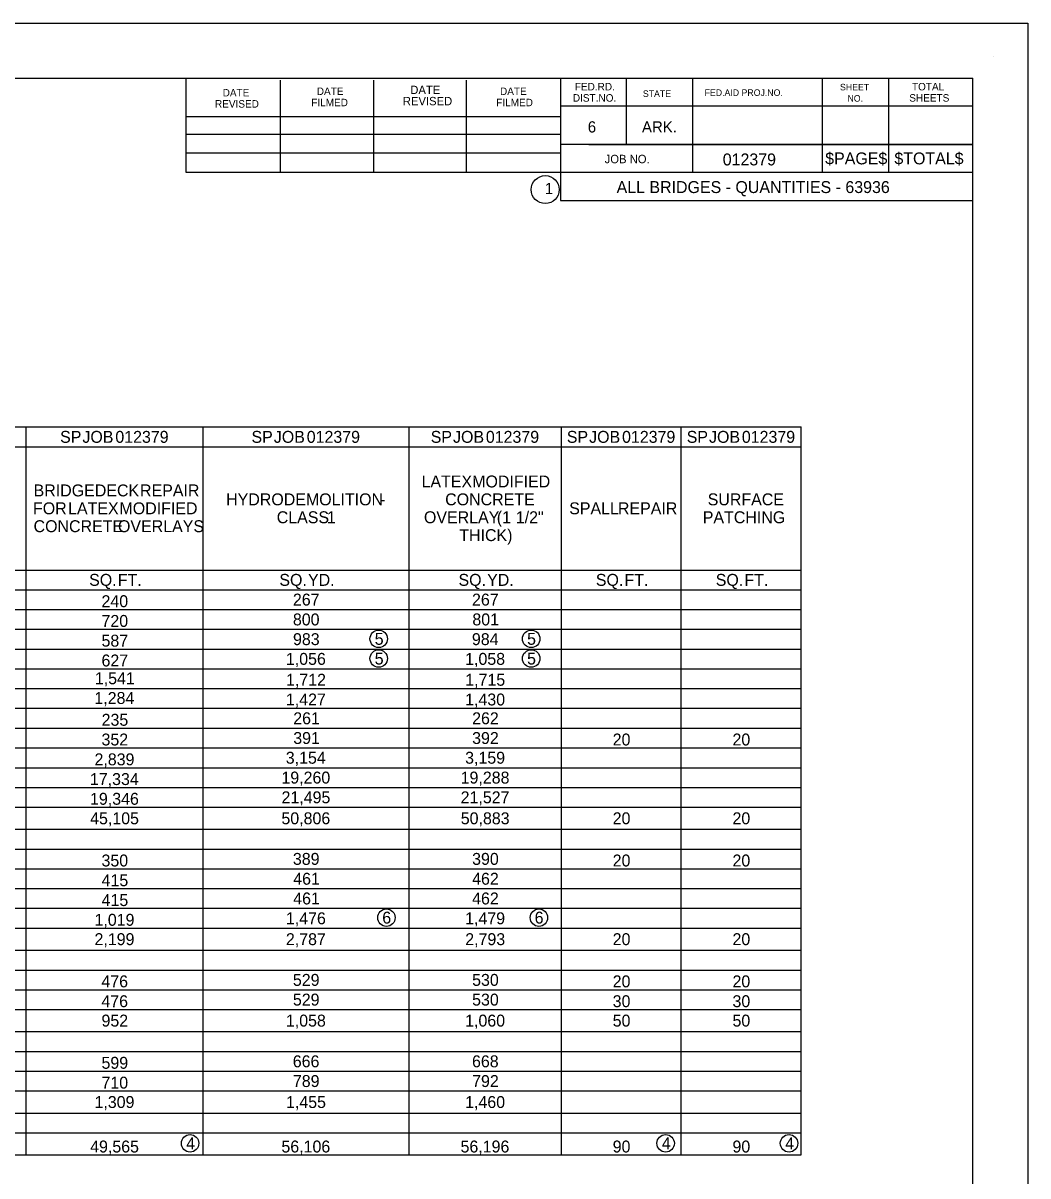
# Model space of a CAD drawing. Extents: x 16 to 1228740, y 11 to 152440.
# Drawn here: x 17.615 to 18.49, y 11.538 to 12.543 of the extents above; entities that cross this region are included whole.
import ezdxf

# ---------------------------------------------------------------- set-up
doc = ezdxf.new("R2010")
doc.units = 0
for name, color, linetype in [('B_Copy In', 7, 'Continuous'), ('B_Text', 7, 'Continuous'), ('R_Border', 7, 'Continuous')]:
    doc.layers.add(name, color=color, linetype=linetype)

msp = doc.modelspace()

# ---------------------------------------------------------------- linework, layer by layer
at = {"layer": 'B_Text'}
for p, q in [((15.9076, 12.1907), (18.2926, 12.1907)), ((17.6172, 11.5559), (17.6172, 12.1907)), ((17.7714, 11.5559), (17.7714, 12.1907)), ((17.9509, 11.5559), (17.9509, 12.1907)), ((18.0837, 11.5559), (18.0837, 12.1907)), ((18.1881, 11.5559), (18.1881, 12.1907)), ((18.2926, 11.5559), (18.2926, 12.1907)), ((18.2926, 11.5559), (18.2926, 12.1907)), ((16.7067, 12.1734), (18.2926, 12.1734)), ((16.7067, 12.0659), (18.2926, 12.0659)), ((15.9076, 12.0487), (18.2926, 12.0487)), ((16.009, 12.0315), (18.2926, 12.0315)), ((16.009, 12.0142), (18.2926, 12.0142)), ((16.009, 11.997), (18.2926, 11.997)), ((16.009, 11.9797), (18.2926, 11.9797)), ((16.009, 11.9625), (18.2926, 11.9625)), ((16.009, 11.9453), (18.2926, 11.9453)), ((16.009, 11.928), (18.2926, 11.928)), ((16.009, 11.9108), (18.2926, 11.9108)), ((16.009, 11.8935), (18.2926, 11.8935)), ((16.009, 11.8763), (18.2926, 11.8763)), ((16.009, 11.8591), (18.2926, 11.8591)), ((15.9076, 11.8398), (18.2926, 11.8398)), ((15.9076, 11.8226), (18.2926, 11.8226)), ((16.009, 11.8053), (18.2926, 11.8053)), ((16.009, 11.7881), (18.2926, 11.7881)), ((16.009, 11.7709), (18.2926, 11.7709)), ((16.009, 11.7536), (18.2926, 11.7536)), ((15.9076, 11.7344), (18.2926, 11.7344)), ((15.9076, 11.7171), (18.2926, 11.7171)), ((16.009, 11.6999), (18.2926, 11.6999)), ((16.009, 11.6826), (18.2926, 11.6826)), ((15.9076, 11.6634), (18.2926, 11.6634)), ((15.9076, 11.6461), (18.2926, 11.6461)), ((16.009, 11.6289), (18.2926, 11.6289)), ((16.009, 11.6117), (18.2926, 11.6117)), ((15.9076, 11.5924), (18.2926, 11.5924)), ((15.9076, 11.5752), (18.2926, 11.5752)), ((15.9076, 11.5559), (18.2926, 11.5559))]:
    msp.add_line(p, q, dxfattribs=at)
for centre in [(17.9245, 12.0059), (18.0574, 12.0059), (17.9245, 11.9887), (18.0574, 11.9887), (17.9312, 11.7628), (18.0641, 11.7628), (17.7601, 11.566), (18.1745, 11.566), (18.2821, 11.566)]:
    msp.add_circle(centre, 0.00762, dxfattribs=at)
at = {"layer": 'R_Border'}
for p, q in [((18.4604, 12.514), (18.4604, 12.514)), ((15.7833, 12.4948), (18.4422, 12.4948)), ((17.7567, 12.4124), (17.7567, 12.4948)), ((17.8389, 12.4124), (17.8389, 12.4931)), ((17.9202, 12.4124), (17.9202, 12.4931)), ((18.0009, 12.4124), (18.0009, 12.4931)), ((18.083, 12.4948), (18.083, 12.3881)), ((18.14, 12.4948), (18.14, 12.4369)), ((18.1979, 12.4948), (18.1979, 12.4124)), ((18.311, 12.4948), (18.311, 12.4124)), ((18.3689, 12.4948), (18.3689, 12.4124)), ((18.4422, 10.7576), (18.4422, 12.4948)), ((18.4422, 12.4703), (18.083, 12.4703)), ((18.4422, 12.4704), (18.4422, 12.4704)), ((17.7567, 12.4613), (18.083, 12.4613)), ((17.7567, 12.4458), (18.083, 12.4458)), ((18.4422, 12.4369), (18.083, 12.4369)), ((18.1077, 12.4369), (18.4422, 12.4369)), ((17.7567, 12.4124), (17.7567, 12.4296)), ((17.7567, 12.4296), (18.083, 12.4296)), ((18.4422, 12.4124), (17.7567, 12.4124)), ((18.083, 12.3881), (18.4422, 12.3881)), ((18.083, 12.3881), (18.4422, 12.3881))]:
    msp.add_line(p, q, dxfattribs=at)
msp.add_lwpolyline([(15.6569, 12.5428), (18.4903, 12.5428), (18.4903, 10.7095), (15.6569, 10.7095)], close=True, dxfattribs=at)
msp.add_circle((18.0696, 12.3976), 0.0122, dxfattribs=at)

# ---------------------------------------------------------------- texts
at = {"layer": 'B_Copy In'}
msp.add_text('ALL BRIDGES - QUANTITIES - 63936', height=0.0104, dxfattribs=at).set_placement((18.1318, 12.3946))
at = {"layer": 'B_Text'}
for s, p in [('SP', (17.6468, 12.1768)), (' JOB', (17.6624, 12.1768)), (' 012379', (17.6911, 12.1768)), ('SP', (17.8136, 12.1768)), (' JOB', (17.8292, 12.1768)), (' 012379', (17.8579, 12.1768)), ('SP', (17.9698, 12.1768)), (' JOB', (17.9854, 12.1768)), (' 012379', (18.014, 12.1768)), ('SP', (18.0884, 12.1768)), (' JOB', (18.104, 12.1768)), (' 012379', (18.1327, 12.1768)), ('SP', (18.1929, 12.1768)), (' JOB', (18.2085, 12.1768)), (' 012379', (18.2371, 12.1768)), ('LATEX', (17.9618, 12.1379)), (' MODIFIED', (18.0021, 12.1379)), ('BRIDGE', (17.6237, 12.1301)), (' DECK', (17.6732, 12.1301)), (' REPAIR', (17.7126, 12.1301)), ('FOR', (17.6232, 12.1145)), (' LATEX', (17.6499, 12.1145)), (' MODIFIED', (17.6947, 12.1145)), ('HYDRODEMOLITION', (17.7915, 12.1223)), (' -', (17.9217, 12.1223)), ('CONCRETE', (17.9824, 12.1223)), ('SPALL', (18.0905, 12.1145)), (' REPAIR', (18.1291, 12.1145)), ('SURFACE', (18.2112, 12.1223)), ('CLASS', (17.8356, 12.1067)), (' 1', (17.8755, 12.1067)), ('OVERLAY', (17.9639, 12.1067)), (' (1', (18.0235, 12.1067)), (' 1/2"', (18.0401, 12.1067)), ('PATCHING', (18.2069, 12.1067)), ('CONCRETE', (17.6237, 12.0989)), (' OVERLAYS', (17.6934, 12.0989)), ('THICK)', (17.9947, 12.0911)), ('SQ.', (17.6721, 12.0521)), (' FT.', (17.6932, 12.0521)), ('SQ.', (17.8379, 12.0521)), (' YD.', (17.859, 12.0521)), ('SQ.', (17.994, 12.0521)), (' YD.', (18.0151, 12.0521)), ('SQ.', (18.1137, 12.0521)), (' FT.', (18.1348, 12.0521)), ('SQ.', (18.2182, 12.0521)), (' FT.', (18.2393, 12.0521)), ('240', (17.6829, 12.0335)), ('267', (17.8497, 12.0349)), ('267', (18.0058, 12.0349)), ('720', (17.6829, 12.0163)), ('800', (17.8497, 12.0176)), ('801', (18.0061, 12.0176)), ('587', (17.6829, 11.9991)), ('983', (17.8498, 12.0004)), ('5', (17.921, 12.0007)), ('984', (18.0057, 12.0004)), ('5', (18.0538, 12.0007)), ('1,056', (17.8436, 11.9832)), ('5', (17.921, 11.9835)), ('1,058', (17.9998, 11.9832)), ('5', (18.0538, 11.9835)), ('627', (17.6829, 11.9818)), ('1,541', (17.6771, 11.9663)), ('1,712', (17.8437, 11.965)), ('1,715', (17.9999, 11.965)), ('1,284', (17.6767, 11.9491)), ('1,427', (17.8436, 11.9478)), ('1,430', (17.9998, 11.9478)), ('235', (17.683, 11.9301)), ('261', (17.85, 11.9314)), ('262', (18.0059, 11.9314)), ('352', (17.6829, 11.9129)), ('391', (17.85, 11.9142)), ('392', (18.0059, 11.9142)), ('20', (18.1284, 11.9129)), ('20', (18.2328, 11.9129)), ('2,839', (17.6768, 11.8956)), ('3,154', (17.8435, 11.897)), ('3,159', (17.9998, 11.897)), ('17,334', (17.6728, 11.8784)), ('19,260', (17.8397, 11.8797)), ('19,288', (17.9959, 11.8797)), ('21,495', (17.8398, 11.8625)), ('21,527', (17.9959, 11.8625)), ('19,346', (17.6729, 11.8612)), ('45,105', (17.673, 11.8442)), ('50,806', (17.8397, 11.8442)), ('50,883', (17.996, 11.8442)), ('20', (18.1284, 11.8442)), ('20', (18.2328, 11.8442)), ('350', (17.6829, 11.8074)), ('389', (17.8497, 11.8088)), ('390', (18.0059, 11.8088)), ('20', (18.1284, 11.8074)), ('20', (18.2328, 11.8074)), ('461', (17.85, 11.7915)), ('462', (18.0059, 11.7915)), ('415', (17.683, 11.7902)), ('415', (17.683, 11.7729)), ('461', (17.85, 11.7743)), ('462', (18.0059, 11.7743)), ('1,019', (17.6768, 11.7557)), ('1,476', (17.8436, 11.757)), ('6', (17.9276, 11.7576)), ('1,479', (17.9998, 11.757)), ('6', (18.0604, 11.7576)), ('2,199', (17.6768, 11.7388)), ('2,787', (17.8436, 11.7388)), ('2,793', (17.9999, 11.7388)), ('20', (18.1284, 11.7388)), ('20', (18.2328, 11.7388)), ('476', (17.6828, 11.702)), ('529', (17.8497, 11.7033)), ('530', (18.0059, 11.7033)), ('20', (18.1284, 11.702)), ('20', (18.2328, 11.702)), ('476', (17.6828, 11.6847)), ('529', (17.8497, 11.6861)), ('530', (18.0059, 11.6861)), ('30', (18.1284, 11.6847)), ('30', (18.2328, 11.6847)), ('952', (17.6829, 11.6678)), ('1,058', (17.8436, 11.6678)), ('1,060', (17.9998, 11.6678)), ('50', (18.1284, 11.6678)), ('50', (18.2328, 11.6678)), ('599', (17.6829, 11.631)), ('666', (17.8496, 11.6323)), ('668', (18.0058, 11.6323)), ('710', (17.6829, 11.6137)), ('789', (17.8497, 11.6151)), ('792', (18.0059, 11.6151)), ('1,309', (17.6768, 11.5968)), ('1,455', (17.8437, 11.5968)), ('1,460', (17.9998, 11.5968)), ('4', (17.7567, 11.5608)), ('4', (18.1712, 11.5608)), ('4', (18.2788, 11.5608)), ('49,565', (17.673, 11.558)), ('56,106', (17.8397, 11.558)), ('56,196', (17.9958, 11.558)), ('90', (18.1284, 11.558)), ('90', (18.2328, 11.558))]:
    msp.add_text(s, height=0.0104, dxfattribs=at).set_placement(p)
at = {"layer": 'R_Border'}
for s, height, p in [('DATE', 0.00652, (17.8705, 12.4801)), ('DATE', 0.00733, (17.952, 12.4809)), ('DATE', 0.00652, (18.0302, 12.4801)), ('FED.RD.', 0.00652, (18.0954, 12.4841)), ('SHEET', 0.0057, (18.3265, 12.4841)), ('TOTAL', 0.00652, (18.3892, 12.4841)), ('REVISED', 0.00652, (17.7818, 12.4691)), ('DATE', 0.00652, (17.7885, 12.4788)), ('FILMED', 0.00652, (17.8657, 12.4703)), ('REVISED', 0.00733, (17.9455, 12.4711)), ('FILMED', 0.00652, (18.0269, 12.4703)), ('DIST.NO.', 0.00652, (18.0937, 12.4743)), ('STATE', 0.0057, (18.1547, 12.4784)), ('FED.AID PROJ.NO.', 0.0057, (18.2085, 12.4793)), ('NO.', 0.0057, (18.333, 12.4743)), ('SHEETS', 0.00652, (18.3869, 12.4743)), ('6', 0.00977, (18.1067, 12.4474)), ('ARK.', 0.00977, (18.1539, 12.4474)), ('JOB NO.', 0.00733, (18.1214, 12.4206)), ('012379', 0.0104, (18.2243, 12.4187)), ('$PAGE$', 0.0104, (18.3136, 12.4196)), ('$TOTAL$', 0.0104, (18.3739, 12.4196)), ('1', 0.00977, (18.0693, 12.3937))]:
    msp.add_text(s, height=height, dxfattribs=at).set_placement(p)

doc.saveas('drawing.dxf')
